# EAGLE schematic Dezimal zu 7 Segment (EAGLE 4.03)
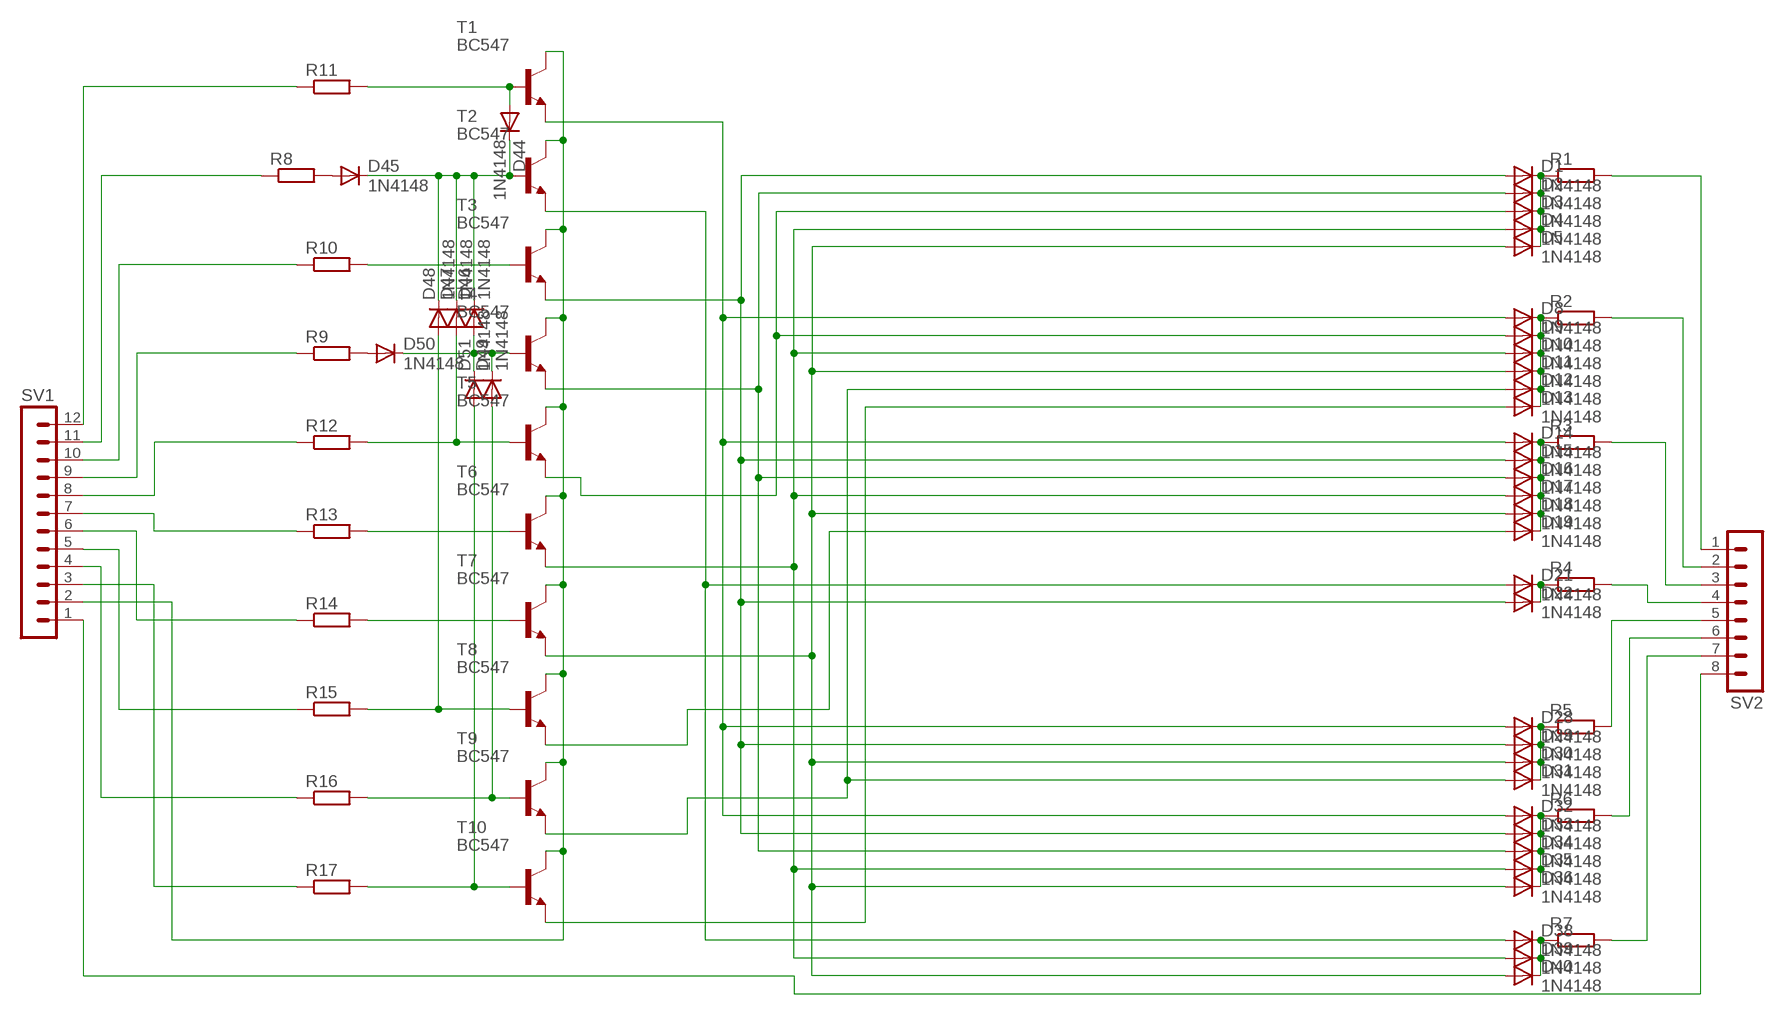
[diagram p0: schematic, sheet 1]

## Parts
D1  1N4148  [DO35-10]
D2  1N4148  [DO35-10]
D3  1N4148  [DO35-10]
D4  1N4148  [DO35-10]
D5  1N4148  [DO35-10]
D8  1N4148  [DO35-10]
D9  1N4148  [DO35-10]
D10  1N4148  [DO35-10]
D11  1N4148  [DO35-10]
D12  1N4148  [DO35-10]
D13  1N4148  [DO35-10]
D14  1N4148  [DO35-10]
D15  1N4148  [DO35-10]
D16  1N4148  [DO35-10]
D17  1N4148  [DO35-10]
D18  1N4148  [DO35-10]
D19  1N4148  [DO35-10]
D21  1N4148  [DO35-10]
D22  1N4148  [DO35-10]
D28  1N4148  [DO35-10]
D29  1N4148  [DO35-10]
D30  1N4148  [DO35-10]
D31  1N4148  [DO35-10]
D32  1N4148  [DO35-10]
D33  1N4148  [DO35-10]
D34  1N4148  [DO35-10]
D35  1N4148  [DO35-10]
D36  1N4148  [DO35-10]
D38  1N4148  [DO35-10]
D39  1N4148  [DO35-10]
D40  1N4148  [DO35-10]
D44  1N4148  [DO35-10]
D45  1N4148  [DO35-10]
D46  1N4148  [DO35-10]
D47  1N4148  [DO35-10]
D48  1N4148  [DO35-10]
D49  1N4148  [DO35-10]
D50  1N4148  [DO35-10]
D51  1N4148  [DO35-10]
R1  R-EU_0204/V2  [0204V]
R2  R-EU_0204/V2  [0204V]
R3  R-EU_0204/V2  [0204V]
R4  R-EU_0204/V2  [0204V]
R5  R-EU_0204/V2  [0204V]
R6  R-EU_0204/V2  [0204V]
R7  R-EU_0204/V2  [0204V]
R8  R-EU_0204/V2  [0204V]
R9  R-EU_0204/V2  [0204V]
R10  R-EU_0204/V2  [0204V]
R11  R-EU_0204/V2  [0204V]
R12  R-EU_0204/V2  [0204V]
R13  R-EU_0204/V2  [0204V]
R14  R-EU_0204/V2  [0204V]
R15  R-EU_0204/V2  [0204V]
R16  R-EU_0204/V2  [0204V]
R17  R-EU_0204/V2  [0204V]
SV1  MA12-1  [MA12-1]
SV2  MA08-1  [MA08-1]
T1  BC547  [TO92]
T2  BC547  [TO92]
T3  BC547  [TO92]
T4  BC547  [TO92]
T5  BC547  [TO92]
T6  BC547  [TO92]
T7  BC547  [TO92]
T8  BC547  [TO92]
T9  BC547  [TO92]
T10  BC547  [TO92]

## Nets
N$1: D21.A D38.A T2.1(E)
N$2: D1.C D2.C D3.C D4.C D5.C R1.1
N$3: D44.A R11.2 T1.2(B)
N$4: D44.C D45.C D46.C D47.C D48.C T2.2(B)
N$5: D3.A D9.A T5.1(E)
N$6: D4.A D10.A D17.A D35.A D39.A T6.1(E)
N$7: D8.C D9.C D10.C D11.C D12.C D13.C R2.1
N$8: D14.C D15.C D16.C D17.C D18.C D19.C R3.1
N$9: D21.C D22.C R4.1
N$10: D28.C D29.C D30.C D31.C R5.1
N$11: D5.A D11.A D18.A D30.A D36.A D40.A T7.1(E)
N$12: D32.C D33.C D34.C D35.C D36.C R6.1
N$13: D38.C D39.C D40.C R7.1
N$14: D8.A D14.A D28.A D32.A T1.1(E)
N$15: D45.A R8.2
N$16: D50.A R9.2
N$17: R1.2 SV2.1
N$18: D1.A D15.A D22.A D29.A D33.A T3.1(E)
N$19: D48.A R15.2 T8.2(B)
N$20: R10.2 T3.2(B)
N$21: D19.A T8.1(E)
N$22: R2.2 SV2.2
N$23: D46.A D49.C D50.C D51.C T4.2(B)
N$24: R13.2 T6.2(B)
N$25: D2.A D16.A D34.A T4.1(E)
N$26: D49.A R16.2 T9.2(B)
N$27: D12.A D31.A T9.1(E)
N$28: R14.2 T7.2(B)
N$29: D47.A R12.2 T5.2(B)
N$30: R3.2 SV2.3
N$31: SV1.2 T1.3(C) T2.3(C) T3.3(C) T4.3(C) T5.3(C) T6.3(C) T7.3(C) T8.3(C) T9.3(C) T10.3(C)
N$32: D51.A R17.2 T10.2(B)
N$33: D13.A T10.1(E)
N$34: R4.2 SV2.4
N$35: R5.2 SV2.5
N$36: R11.1 SV1.12
N$37: R8.1 SV1.11
N$38: R10.1 SV1.10
N$39: R9.1 SV1.9
N$40: R12.1 SV1.8
N$41: R13.1 SV1.7
N$42: R14.1 SV1.6
N$43: R15.1 SV1.5
N$44: R16.1 SV1.4
N$45: R17.1 SV1.3
N$46: SV1.1 SV2.8
N$47: R6.2 SV2.6
N$48: R7.2 SV2.7

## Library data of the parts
D1-D5 D8-D19 D21 D22 D28-D36 D38-D40 D44-D51 = diode:1N4148: DIODE
R1-R17 = rcl:R-EU_: RESISTOR, European symbol
SV1 = con-lstb:MA12-1: PIN HEADER
SV2 = con-lstb:MA08-1: PIN HEADER
T1-T10 = transistor-npn:BC547: NPN TRANSISTOR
